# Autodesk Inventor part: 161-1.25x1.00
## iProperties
Created: 2007-06
Part Number: 161-1.25x1.00
Document SubType Name: Modeling
Designer: btaylor
Density: 1 g/cm^3
Author: btaylor
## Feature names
1. Extrusion1
2. Extrusion2
3. Extrusion3
4. Extrusion4
5. Extrusion5
6. Fillet1
7. Fillet2
8. Fillet3
9. Extrusion6
10. Extrusion7
11. Extrusion8
12. Extrusion9
13. Extrusion10
14. Fillet6
15. Fillet7
16. Chamfer1
17. Chamfer2
18. Chamfer3
19. Fillet8
20. Fillet9
21. Fillet10
22. Fillet11
23. Fillet12
24. Fillet13
